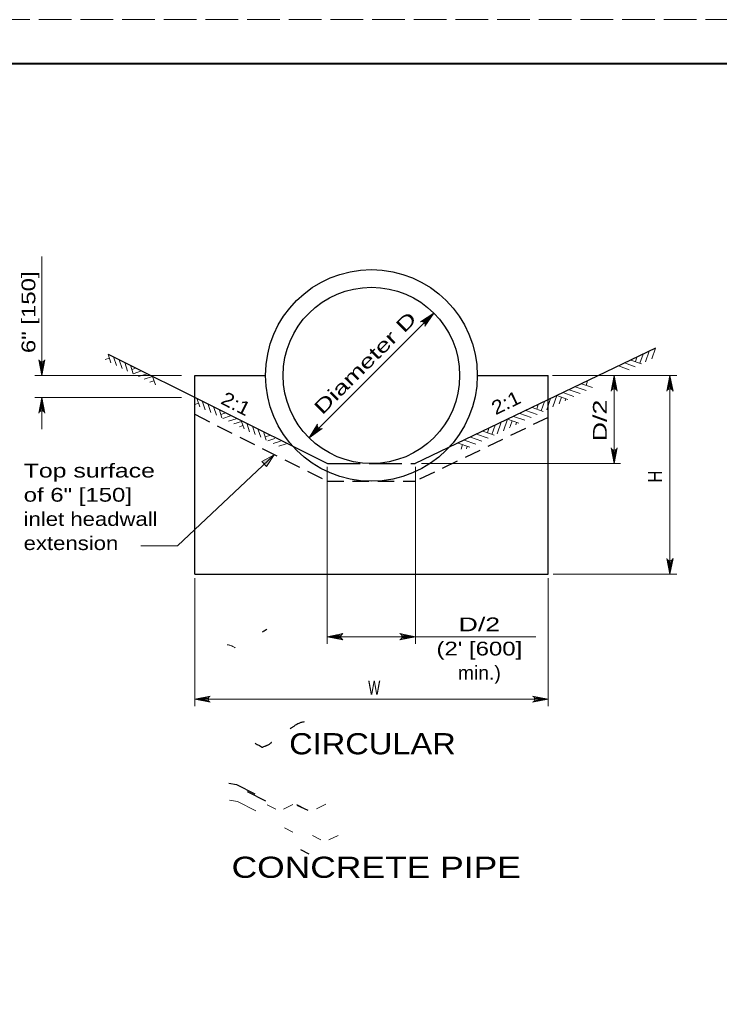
# Model space of a CAD drawing. Extents: x 685.4 to 719.4, y 1059.8 to 1105.8.
# Drawn here: x 698.08 to 706.01, y 1094.73 to 1105.77 of the extents above; entities that cross this region are included whole.
import ezdxf
from ezdxf.enums import TextEntityAlignment as Align

# ---------------------------------------------------------------- set-up
doc = ezdxf.new("R2010")
doc.units = 0
doc.header["$LTSCALE"] = 0.062
for name, pattern in [('LONG_DASHED', [7.5, 6, -1.5]), ('MEDIUM_DASHED', [4.5, 3, -1.5]), ('SHORT_DASHED', [2.7, 1.5, -1.2])]:
    doc.linetypes.add(name, pattern=pattern)
doc.layers.add('1', color=7, linetype='Continuous', lineweight=13)

msp = doc.modelspace()

# ---------------------------------------------------------------- hatches: boundary and pattern name
at = {"layer": '1'}
msp.add_hatch(color=256, dxfattribs=at).paths.add_polyline_path([(700.828, 1100.76033), (700.96825, 1100.839), (700.8815, 1100.70358)])

# ---------------------------------------------------------------- linework, layer by layer
at = {"layer": '1', "lineweight": 25}
for p, q in [((687.44108, 1105.27067), (718.94108, 1105.27067)), ((699.08717, 1101.97925), (701.57142, 1100.738)), ((705.28758, 1102.04608), (702.56675, 1100.738)), ((700.06817, 1099.48433), (700.06817, 1101.73742)), ((700.06817, 1101.73742), (700.87033, 1101.73742)), ((703.26917, 1101.73742), (704.07133, 1101.73742)), ((704.07133, 1099.48433), (704.07133, 1101.73742)), ((700.06817, 1099.48433), (704.07133, 1099.48433)), ((700.661, 1097.0235), (700.86833, 1096.91825)), ((701.22675, 1096.86642), (701.34908, 1096.81225)), ((701.26767, 1096.3645), (701.36183, 1096.31583))]:
    msp.add_line(p, q, dxfattribs=at)
at = {"layer": '1'}
for p, q in [((698.33667, 1103.08342), (698.33667, 1101.73742)), ((701.363, 1101.03075), (702.7765, 1102.44408)), ((702.64433, 1102.347), (702.7765, 1102.44408)), ((702.65608, 1102.344), (702.7765, 1102.44408)), ((702.66825, 1102.33583), (702.7765, 1102.44408)), ((702.67508, 1102.32658), (702.7765, 1102.44408)), ((702.67908, 1102.31492), (702.7765, 1102.44408)), ((699.08717, 1101.97925), (699.11992, 1101.87967)), ((705.11158, 1101.87542), (705.14792, 1101.97892)), ((705.17575, 1101.89275), (705.21775, 1102.0125)), ((705.24575, 1101.92667), (705.28758, 1102.04608)), ((698.31425, 1101.89767), (698.33667, 1101.73742)), ((698.32533, 1101.89225), (698.33667, 1101.73742)), ((698.36142, 1101.8995), (698.33667, 1101.73742)), ((698.351, 1101.89342), (698.33667, 1101.73742)), ((698.33667, 1101.89058), (698.33667, 1101.73742)), ((699.05533, 1101.91625), (699.10275, 1101.93183)), ((699.11358, 1101.88283), (699.11842, 1101.88442)), ((699.15017, 1101.94742), (699.18267, 1101.8485)), ((699.21308, 1101.91567), (699.2455, 1101.81725)), ((699.27625, 1101.88375), (699.30842, 1101.78592)), ((704.93825, 1101.87817), (705.05867, 1101.83592)), ((705.00808, 1101.91175), (705.12817, 1101.86958)), ((705.05975, 1101.89358), (705.07792, 1101.94525)), ((699.33925, 1101.85192), (699.37117, 1101.75483)), ((699.35475, 1101.8045), (699.40217, 1101.82008)), ((699.37042, 1101.75708), (699.46533, 1101.78825)), ((699.43167, 1101.72467), (699.52825, 1101.7565)), ((704.86825, 1101.84442), (704.98908, 1101.80208)), ((699.91967, 1101.73742), (698.258, 1101.73742)), ((699.55942, 1101.66167), (699.60683, 1101.67725)), ((704.11908, 1101.73742), (705.52967, 1101.73742)), ((704.44908, 1101.64292), (704.57242, 1101.59975)), ((704.50075, 1101.62483), (704.51892, 1101.6765)), ((704.79458, 1101.57525), (704.81942, 1101.73742)), ((704.805, 1101.58142), (704.81942, 1101.73742)), ((704.81942, 1101.58425), (704.81942, 1101.73742)), ((704.83075, 1101.58258), (704.81942, 1101.73742)), ((704.84183, 1101.57717), (704.81942, 1101.73742)), ((705.42625, 1101.57525), (705.451, 1101.73742)), ((705.43658, 1101.58142), (705.451, 1101.73742)), ((705.451, 1101.58425), (705.451, 1101.73742)), ((705.46233, 1101.58258), (705.451, 1101.73742)), ((705.47342, 1101.57717), (705.451, 1101.73742)), ((704.23942, 1101.54217), (704.364, 1101.49842)), ((704.30925, 1101.57575), (704.4335, 1101.53217)), ((704.37925, 1101.60942), (704.503, 1101.566)), ((699.91967, 1101.4875), (698.258, 1101.4875)), ((698.31183, 1101.32542), (698.33667, 1101.4875)), ((698.32225, 1101.33158), (698.33667, 1101.4875)), ((698.33667, 1101.4875), (698.33667, 1101.12642)), ((698.33667, 1101.33442), (698.33667, 1101.4875)), ((698.348, 1101.33275), (698.33667, 1101.4875)), ((698.35908, 1101.32733), (698.33667, 1101.4875)), ((700.06792, 1101.40842), (700.111, 1101.42258)), ((700.09533, 1101.47008), (700.12492, 1101.38008)), ((700.15842, 1101.43825), (700.18783, 1101.34883)), ((703.99358, 1101.33792), (704.02992, 1101.44142)), ((704.05542, 1101.34858), (704.09983, 1101.475)), ((704.1255, 1101.38258), (704.16958, 1101.50858)), ((704.16958, 1101.50858), (704.29467, 1101.46483)), ((704.19542, 1101.41658), (704.20242, 1101.43667)), ((704.20317, 1101.43875), (704.22133, 1101.49042)), ((704.26558, 1101.45067), (704.27317, 1101.47233)), ((700.22142, 1101.40642), (700.2505, 1101.31775)), ((700.2845, 1101.3745), (700.31342, 1101.28642)), ((700.3475, 1101.34267), (700.37625, 1101.25517)), ((700.36308, 1101.29533), (700.41042, 1101.31092)), ((703.75033, 1101.307), (703.87775, 1101.26233)), ((703.82025, 1101.34058), (703.94725, 1101.29608)), ((703.89008, 1101.37417), (704.01667, 1101.32983)), ((703.94183, 1101.356), (703.95992, 1101.40775)), ((700.38617, 1101.25025), (700.47358, 1101.279)), ((700.44975, 1101.21867), (700.53658, 1101.24717)), ((700.51333, 1101.18708), (700.5995, 1101.21533)), ((700.5995, 1101.21533), (700.6275, 1101.13033)), ((703.49533, 1101.07658), (703.54083, 1101.20625)), ((703.56533, 1101.11058), (703.61058, 1101.23983)), ((703.61058, 1101.23983), (703.73892, 1101.19492)), ((703.64417, 1101.17), (703.66233, 1101.22167)), ((703.68042, 1101.27342), (703.80825, 1101.22858)), ((703.70542, 1101.17867), (703.71417, 1101.2035)), ((700.577, 1101.1555), (700.61508, 1101.168)), ((700.6625, 1101.18358), (700.69025, 1101.09908)), ((700.7255, 1101.15175), (700.75308, 1101.06792)), ((700.78858, 1101.11992), (700.816, 1101.03667)), ((700.85158, 1101.08808), (700.87875, 1101.0055)), ((701.45708, 1101.16233), (701.363, 1101.03067)), ((701.46133, 1101.15075), (701.363, 1101.03067)), ((701.46842, 1101.14183), (701.363, 1101.03067)), ((701.48083, 1101.13392), (701.363, 1101.03067)), ((701.49258, 1101.13125), (701.363, 1101.03067)), ((703.33108, 1101.10542), (703.461, 1101.05992)), ((703.38283, 1101.08733), (703.401, 1101.139)), ((703.43458, 1101.06917), (703.47092, 1101.17275)), ((703.63525, 1101.14458), (703.64342, 1101.16792)), ((700.86717, 1101.04075), (700.91458, 1101.05625)), ((700.89525, 1100.99725), (700.97767, 1101.02442)), ((700.95875, 1100.96567), (701.04067, 1100.99258)), ((703.12142, 1101.00467), (703.2525, 1100.95867)), ((703.19133, 1101.03825), (703.322, 1100.99242)), ((703.26125, 1101.07183), (703.39158, 1101.02625)), ((701.02242, 1100.934), (701.10367, 1100.96075)), ((703.05167, 1100.97108), (703.18317, 1100.92492)), ((703.08517, 1100.90133), (703.10333, 1100.95292)), ((703.14525, 1100.9065), (703.15517, 1100.93475)), ((704.797, 1100.89825), (704.81942, 1100.738)), ((704.80808, 1100.89275), (704.81942, 1100.738)), ((704.84417, 1100.90008), (704.81942, 1100.738)), ((704.83375, 1100.894), (704.81942, 1100.738)), ((704.81942, 1100.89117), (704.81942, 1100.738)), ((700.96825, 1100.839), (699.87458, 1099.808)), ((701.57, 1098.69767), (701.57, 1100.70075)), ((702.5695, 1098.69767), (702.5695, 1100.70075)), ((702.6375, 1100.738), (704.89183, 1100.738)), ((704.07133, 1100.14958), (704.07133, 1099.48433)), ((699.45817, 1099.808), (699.87458, 1099.808)), ((705.42858, 1099.64458), (705.451, 1099.48433)), ((705.43967, 1099.63917), (705.451, 1099.48433)), ((705.47575, 1099.6465), (705.451, 1099.48433)), ((705.46542, 1099.64033), (705.451, 1099.48433)), ((705.451, 1099.6375), (705.451, 1099.48433)), ((700.06817, 1099.44158), (700.06817, 1097.98967)), ((704.07133, 1099.44158), (704.07133, 1097.98967)), ((704.12692, 1099.48433), (705.52967, 1099.48433)), ((701.73025, 1098.79875), (701.57, 1098.77633)), ((701.72483, 1098.78767), (701.57, 1098.77633)), ((701.57, 1098.77633), (703.9335, 1098.77633)), ((701.72317, 1098.77633), (701.57, 1098.77633)), ((701.726, 1098.762), (701.57, 1098.77633)), ((701.73217, 1098.75158), (701.57, 1098.77633)), ((702.40742, 1098.75158), (702.5695, 1098.77633)), ((702.40925, 1098.79875), (702.5695, 1098.77633)), ((702.4135, 1098.762), (702.5695, 1098.77633)), ((702.41467, 1098.78767), (702.5695, 1098.77633)), ((702.41633, 1098.77633), (702.5695, 1098.77633)), ((700.22842, 1098.09075), (700.06817, 1098.06833)), ((700.223, 1098.07967), (700.06817, 1098.06833)), ((700.22133, 1098.06833), (700.06817, 1098.06833)), ((700.22417, 1098.054), (700.06817, 1098.06833)), ((700.23033, 1098.04358), (700.06817, 1098.06833)), ((700.06817, 1098.06833), (704.07133, 1098.06833)), ((703.90917, 1098.04358), (704.07133, 1098.06833)), ((703.91108, 1098.09075), (704.07133, 1098.06833)), ((703.91533, 1098.054), (704.07133, 1098.06833)), ((703.9165, 1098.07967), (704.07133, 1098.06833)), ((703.91817, 1098.06833), (704.07133, 1098.06833)), ((700.89025, 1096.87108), (700.9855, 1096.823)), ((701.18092, 1096.87417), (701.07533, 1096.82342)), ((701.22317, 1096.8735), (701.31833, 1096.82542)), ((701.55383, 1096.87767), (701.44825, 1096.82683)), ((701.08667, 1096.61208), (701.18092, 1096.56342)), ((701.40292, 1096.52217), (701.49817, 1096.47408)), ((701.69358, 1096.52525), (701.588, 1096.4745))]:
    msp.add_line(p, q, dxfattribs=at)
at = {"layer": '1', "linetype": 'MEDIUM_DASHED', "lineweight": 25}
for p, q in [((700.06817, 1101.29667), (701.57, 1100.53808)), ((704.07133, 1101.26025), (702.5695, 1100.53808)), ((701.57, 1100.53808), (702.5695, 1100.53808))]:
    msp.add_line(p, q, dxfattribs=at)
at = {"layer": '1', "linetype": 'LONG_DASHED', "lineweight": 25}
msp.add_line((701.57142, 1100.738), (702.56675, 1100.738), dxfattribs=at)
at = {"layer": '1', "linetype": 'LONG_DASHED'}
msp.add_lwpolyline([(685.44108, 1083.77067), (719.44108, 1083.77067), (719.44108, 1105.77067), (685.44108, 1105.77067)], close=True, dxfattribs=at)
at = {"layer": '1', "lineweight": 40}
msp.add_lwpolyline([(687.44108, 1105.27067), (718.94108, 1105.27067), (718.94108, 1084.27067), (687.44108, 1084.27067)], close=True, dxfattribs=at)
at = {"layer": '1'}
for points in [[(702.62633, 1102.344), (702.7765, 1102.44408), (702.67642, 1102.29392)], [(698.372, 1101.91442), (698.33667, 1101.73742), (698.30125, 1101.91442)], [(699.49533, 1101.69308), (699.59125, 1101.72467), (699.62242, 1101.62983)], [(704.784, 1101.56042), (704.81942, 1101.73742), (704.85475, 1101.56042)], [(704.81942, 1101.73742), (704.81942, 1101.111), (704.81942, 1100.738)], [(705.41558, 1101.56042), (705.451, 1101.73742), (705.48642, 1101.56042)], [(705.451, 1101.73742), (705.451, 1100.42275), (705.451, 1099.48433)], [(698.30125, 1101.3105), (698.33667, 1101.4875), (698.372, 1101.3105)], [(701.5105, 1101.13475), (701.363, 1101.03067), (701.45917, 1101.18342)], [(704.85475, 1100.915), (704.81942, 1100.738), (704.784, 1100.915)], [(705.48642, 1099.66133), (705.451, 1099.48433), (705.41558, 1099.66133)], [(701.747, 1098.741), (701.57, 1098.77633), (701.747, 1098.81175)], [(702.3925, 1098.741), (702.5695, 1098.77633), (702.3925, 1098.81175)], [(700.24517, 1098.033), (700.06817, 1098.06833), (700.24517, 1098.10375)], [(703.89433, 1098.033), (704.07133, 1098.06833), (703.89433, 1098.10375)], [(700.46283, 1096.92358), (700.55142, 1096.909), (700.75875, 1096.80367)]]:
    msp.add_lwpolyline(points, dxfattribs=at)
msp.add_lwpolyline([(700.828, 1100.76033), (700.96825, 1100.839), (700.8815, 1100.70358)], close=True, dxfattribs=at)
at = {"layer": '1', "lineweight": 25}
for points in [[(700.83675, 1098.83133), (700.843, 1098.83458), (700.84508, 1098.836), (700.84883, 1098.83867), (700.854, 1098.84175), (700.85717, 1098.84375), (700.86175, 1098.8465), (700.86542, 1098.84892), (700.86983, 1098.85158), (700.873, 1098.85333), (700.87667, 1098.85642), (700.87908, 1098.85842), (700.88117, 1098.85975), (700.88425, 1098.86175)], [(701.30675, 1097.81033), (701.29733, 1097.80958), (701.28867, 1097.80783), (701.2795, 1097.80567), (701.27058, 1097.80292), (701.26217, 1097.79975), (701.24925, 1097.79475), (701.23658, 1097.788), (701.22692, 1097.78342), (701.21992, 1097.78), (701.21617, 1097.77758), (701.207, 1097.77283), (701.201, 1097.76825), (701.19758, 1097.76583), (701.19033, 1097.76033), (701.18275, 1097.75517), (701.17683, 1097.75125), (701.17167, 1097.74833), (701.16425, 1097.74333), (701.15908, 1097.74), (701.14817, 1097.73142)], [(700.45492, 1097.11533), (700.5435, 1097.10067), (700.75083, 1096.99542)]]:
    msp.add_lwpolyline(points, dxfattribs=at)
at = {"layer": '1'}
for centre, start, end in [((702.64129, 1102.30881), 337.08479, 112.91092), ((698.3366, 1101.92869), 202.08782, 337.91395), ((704.81942, 1101.5461), 22.08782, 157.91395), ((705.45104, 1101.5461), 22.08782, 157.91395), ((698.33668, 1101.29624), 22.08782, 157.91395), ((701.49466, 1101.16948), 158.58888, 294.41501), ((704.81934, 1100.92926), 202.08782, 337.91395), ((705.45096, 1099.67566), 202.08782, 337.91395), ((701.76129, 1098.7764), 112.08782, 247.91395), ((702.37823, 1098.7764), 292.08605, 67.91218), ((700.2595, 1098.0684), 112.08782, 247.91395), ((703.88002, 1098.0684), 292.08605, 67.91218)]:
    msp.add_arc(centre, 0.0382, start, end, dxfattribs=at)
at = {"layer": '1', "linetype": 'SHORT_DASHED'}
msp.add_arc((700.41033, 1098.47648), 0.21007, 55.79124, 89.52541, dxfattribs=at)
at = {"layer": '1', "lineweight": 25}
for major_axis in [(1.19944, 0), (0.99953, 0)]:
    msp.add_ellipse((702.06976, 1101.7374), major_axis=major_axis, ratio=0.999895, dxfattribs=at)
for points in [[(700.75317, 1097.5695), (700.76683, 1097.55808), (700.7755, 1097.55333), (700.79275, 1097.54625), (700.80117, 1097.54192), (700.80867, 1097.53775), (700.817, 1097.53242), (700.82042, 1097.53025), (700.82317, 1097.5285), (700.82717, 1097.52675), (700.831, 1097.52567), (700.83358, 1097.52567), (700.83742, 1097.52583), (700.84125, 1097.52675), (700.84358, 1097.52767), (700.86117, 1097.53442), (700.87283, 1097.54108), (700.8805, 1097.54383), (700.88808, 1097.547), (700.89967, 1097.551), (700.91467, 1097.56025)], [(700.91467, 1097.56025), (700.92742, 1097.5695), (700.93767, 1097.58017), (700.94167, 1097.58342)]]:
    msp.add_spline(points, degree=3, dxfattribs=at)

# ---------------------------------------------------------------- texts
at = {"layer": '1'}
for s, rotation, width, p in [('6" [150]', 90, 1.3, (698.26317, 1101.99033)), ('Diameter D', 44.997, 1.45, (701.51342, 1101.28267)), ('2:1', 333.203, 1.15, (700.35142, 1101.42217)), ('2:1', 25.677, 1.15, (703.47683, 1101.28575)), ('D/2', 90, 1.45, (704.7355, 1100.99167)), ('H', 90, 0.9, (705.36025, 1100.5235))]:
    msp.add_text(s, height=0.156, rotation=rotation, dxfattribs=dict(at, width=width)).set_placement(p)
for s, height, width, p in [('Top surface', 0.156, 1.35, (698.13075, 1100.58058)), ('of 6" [150]', 0.156, 1.3, (698.13075, 1100.30658)), ('inlet headwall', 0.156, 1.2, (698.13075, 1100.03258)), ('extension', 0.156, 1.2, (698.13075, 1099.75858)), ('W', 0.156, 0.7, (702.03275, 1098.12117)), ('CIRCULAR', 0.24, 1.15, (701.13833, 1097.44358)), ('CONCRETE PIPE', 0.24, 1.25, (700.48567, 1096.044))]:
    msp.add_text(s, height=height, dxfattribs=dict(at, width=width)).set_placement(p)
for s, width, p in [('D/2', 1.45, (703.29246, 1098.838)), ("(2' [600]", 1.3, (703.29242, 1098.564)), ('min.)', 1.05, (703.29246, 1098.29))]:
    msp.add_text(s, height=0.156, dxfattribs=dict(at, width=width)).set_placement(p, align=Align.CENTER)

doc.saveas('drawing.dxf')
